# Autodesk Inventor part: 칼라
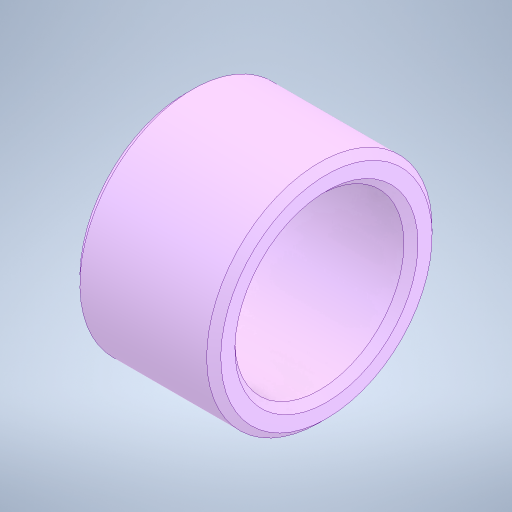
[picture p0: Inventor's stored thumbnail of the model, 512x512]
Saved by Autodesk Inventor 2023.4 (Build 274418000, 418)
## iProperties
Created: 2024-05
Part Number: 칼라
Material: 강철, 합금
Document SubType Name: Modeling
Designer: user
Density: 7.73 g/cm^3
Appearance: 기본값
Author: jhkim
Sending System: Autodesk Inventor 2025
Preprocessor: ST-DEVELOPER v20
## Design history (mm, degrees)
feature "솔리드1"
node "솔리드2"
